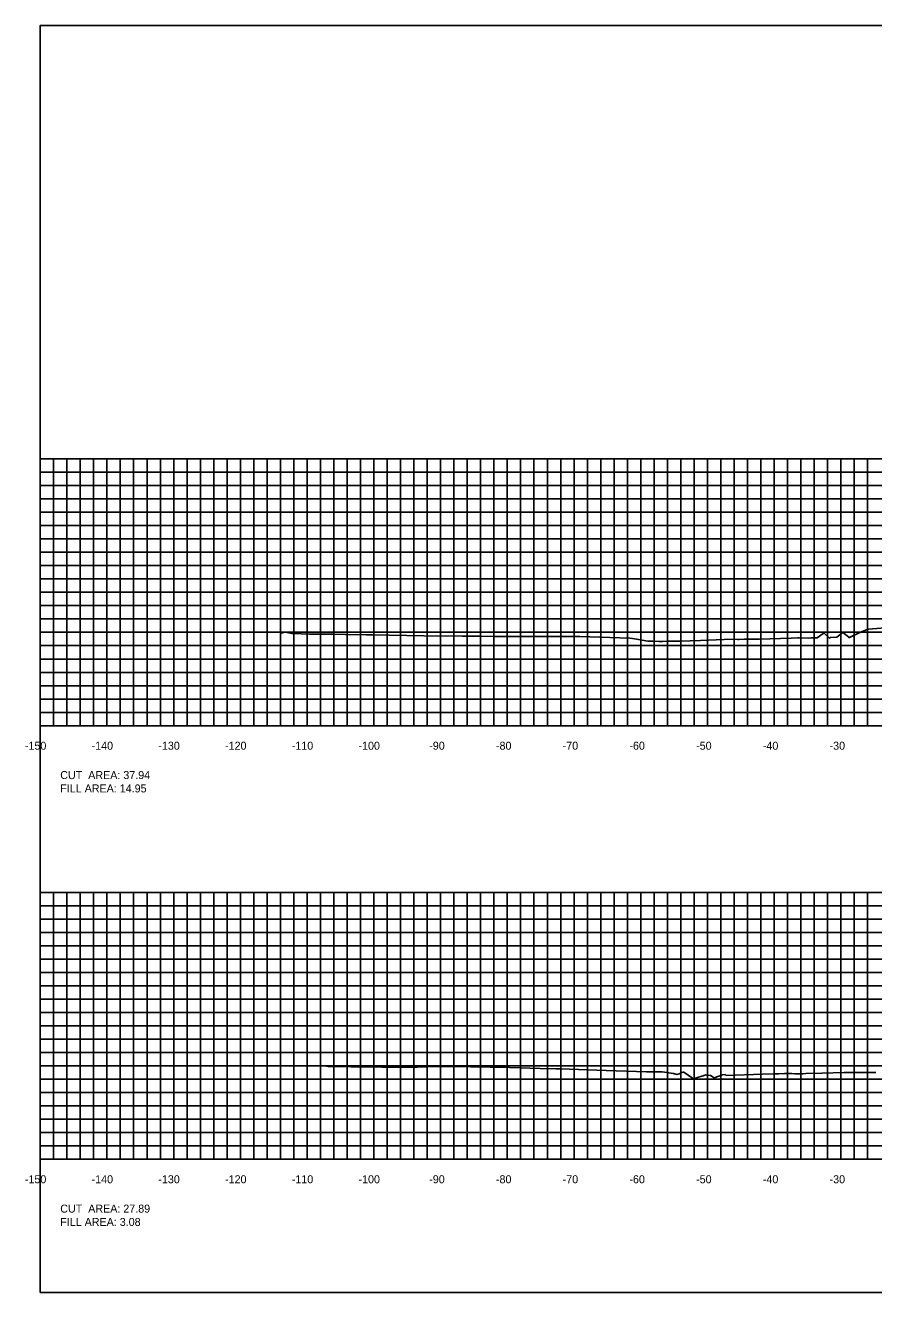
# Model space of a CAD drawing. Extents: x 1797652 to 1804159, y 242516 to 246906.
# Drawn here: x 1802492.3 to 1802619.4, y 242516 to 242706 of the extents above; entities that cross this region are included whole.
import ezdxf

# ---------------------------------------------------------------- set-up
doc = ezdxf.new("R2010")
doc.units = 0
for name, color, linetype in [('10', 7, 'Continuous'), ('60', 7, 'Continuous'), ('Level 62', 7, 'Continuous'), ('M-ROADS', 7, 'Continuous')]:
    doc.layers.add(name, color=color, linetype=linetype)

msp = doc.modelspace()

# ---------------------------------------------------------------- linework, layer by layer
msp.add_lwpolyline([(1802494.49, 242516), (1802794.49, 242516), (1802794.49, 242706), (1802494.49, 242706)], close=True)
at = {"layer": '60'}
for p, q in [((1802494.43, 242641), (1802494.49, 242641)), ((1802494.49, 242601), (1802494.49, 242641)), ((1802494.43, 242631), (1802494.49, 242631)), ((1802494.43, 242621), (1802494.49, 242621)), ((1802494.43, 242611), (1802494.49, 242611)), ((1802494.43, 242601), (1802494.49, 242601)), ((1802494.49, 242601), (1802794.49, 242601)), ((1802494.49, 242600.94), (1802494.49, 242601)), ((1802504.49, 242600.94), (1802504.49, 242601)), ((1802514.49, 242600.94), (1802514.49, 242601)), ((1802524.49, 242600.94), (1802524.49, 242601)), ((1802534.49, 242600.94), (1802534.49, 242601)), ((1802544.49, 242600.94), (1802544.49, 242601)), ((1802554.49, 242600.94), (1802554.49, 242601)), ((1802564.49, 242600.94), (1802564.49, 242601)), ((1802574.49, 242600.94), (1802574.49, 242601)), ((1802584.49, 242600.94), (1802584.49, 242601)), ((1802594.49, 242600.94), (1802594.49, 242601)), ((1802604.49, 242600.94), (1802604.49, 242601)), ((1802614.49, 242600.94), (1802614.49, 242601)), ((1802494.43, 242576), (1802494.49, 242576)), ((1802494.49, 242536), (1802494.49, 242576)), ((1802494.43, 242566), (1802494.49, 242566)), ((1802494.43, 242556), (1802494.49, 242556)), ((1802494.43, 242546), (1802494.49, 242546)), ((1802494.43, 242536), (1802494.49, 242536)), ((1802494.49, 242536), (1802794.49, 242536)), ((1802494.49, 242535.94), (1802494.49, 242536)), ((1802504.49, 242535.94), (1802504.49, 242536)), ((1802514.49, 242535.94), (1802514.49, 242536)), ((1802524.49, 242535.94), (1802524.49, 242536)), ((1802534.49, 242535.94), (1802534.49, 242536)), ((1802544.49, 242535.94), (1802544.49, 242536)), ((1802554.49, 242535.94), (1802554.49, 242536)), ((1802564.49, 242535.94), (1802564.49, 242536)), ((1802574.49, 242535.94), (1802574.49, 242536)), ((1802584.49, 242535.94), (1802584.49, 242536)), ((1802594.49, 242535.94), (1802594.49, 242536)), ((1802604.49, 242535.94), (1802604.49, 242536)), ((1802614.49, 242535.94), (1802614.49, 242536))]:
    msp.add_line(p, q, dxfattribs=at)
at = {"layer": 'Level 62'}
for p, q in [((1802494.49, 242641), (1802794.49, 242641)), ((1802494.49, 242601), (1802494.49, 242641)), ((1802496.49, 242601), (1802496.49, 242641)), ((1802498.49, 242601), (1802498.49, 242641)), ((1802500.49, 242601), (1802500.49, 242641)), ((1802502.49, 242601), (1802502.49, 242641)), ((1802504.49, 242601), (1802504.49, 242641)), ((1802506.49, 242601), (1802506.49, 242641)), ((1802508.49, 242601), (1802508.49, 242641)), ((1802510.49, 242601), (1802510.49, 242641)), ((1802512.49, 242601), (1802512.49, 242641)), ((1802514.49, 242601), (1802514.49, 242641)), ((1802516.49, 242601), (1802516.49, 242641)), ((1802518.49, 242601), (1802518.49, 242641)), ((1802520.49, 242601), (1802520.49, 242641)), ((1802522.49, 242601), (1802522.49, 242641)), ((1802524.49, 242601), (1802524.49, 242641)), ((1802526.49, 242601), (1802526.49, 242641)), ((1802528.49, 242601), (1802528.49, 242641)), ((1802530.49, 242601), (1802530.49, 242641)), ((1802532.49, 242601), (1802532.49, 242641)), ((1802534.49, 242601), (1802534.49, 242641)), ((1802536.49, 242601), (1802536.49, 242641)), ((1802538.49, 242601), (1802538.49, 242641)), ((1802540.49, 242601), (1802540.49, 242641)), ((1802542.49, 242601), (1802542.49, 242641)), ((1802544.49, 242601), (1802544.49, 242641)), ((1802546.49, 242601), (1802546.49, 242641)), ((1802548.49, 242601), (1802548.49, 242641)), ((1802550.49, 242601), (1802550.49, 242641)), ((1802552.49, 242601), (1802552.49, 242641)), ((1802554.49, 242601), (1802554.49, 242641)), ((1802556.49, 242601), (1802556.49, 242641)), ((1802558.49, 242601), (1802558.49, 242641)), ((1802560.49, 242601), (1802560.49, 242641)), ((1802562.49, 242601), (1802562.49, 242641)), ((1802564.49, 242601), (1802564.49, 242641)), ((1802566.49, 242601), (1802566.49, 242641)), ((1802568.49, 242601), (1802568.49, 242641)), ((1802570.49, 242601), (1802570.49, 242641)), ((1802572.49, 242601), (1802572.49, 242641)), ((1802574.49, 242601), (1802574.49, 242641)), ((1802576.49, 242601), (1802576.49, 242641)), ((1802578.49, 242601), (1802578.49, 242641)), ((1802580.49, 242601), (1802580.49, 242641)), ((1802582.49, 242601), (1802582.49, 242641)), ((1802584.49, 242601), (1802584.49, 242641)), ((1802586.49, 242601), (1802586.49, 242641)), ((1802588.49, 242601), (1802588.49, 242641)), ((1802590.49, 242601), (1802590.49, 242641)), ((1802592.49, 242601), (1802592.49, 242641)), ((1802594.49, 242601), (1802594.49, 242641)), ((1802596.49, 242601), (1802596.49, 242641)), ((1802598.49, 242601), (1802598.49, 242641)), ((1802600.49, 242601), (1802600.49, 242641)), ((1802602.49, 242601), (1802602.49, 242641)), ((1802604.49, 242601), (1802604.49, 242641)), ((1802606.49, 242601), (1802606.49, 242641)), ((1802608.49, 242601), (1802608.49, 242641)), ((1802610.49, 242601), (1802610.49, 242641)), ((1802612.49, 242601), (1802612.49, 242641)), ((1802614.49, 242601), (1802614.49, 242641)), ((1802616.49, 242601), (1802616.49, 242641)), ((1802618.49, 242601), (1802618.49, 242641)), ((1802494.49, 242639), (1802794.49, 242639)), ((1802494.49, 242637), (1802794.49, 242637)), ((1802494.49, 242635), (1802794.49, 242635)), ((1802494.49, 242633), (1802794.49, 242633)), ((1802494.49, 242631), (1802794.49, 242631)), ((1802494.49, 242629), (1802794.49, 242629)), ((1802494.49, 242627), (1802794.49, 242627)), ((1802494.49, 242625), (1802794.49, 242625)), ((1802494.49, 242623), (1802794.49, 242623)), ((1802494.49, 242621), (1802794.49, 242621)), ((1802494.49, 242619), (1802794.49, 242619)), ((1802494.49, 242617), (1802794.49, 242617)), ((1802494.49, 242615), (1802794.49, 242615)), ((1802494.49, 242613), (1802794.49, 242613)), ((1802494.49, 242611), (1802794.49, 242611)), ((1802494.49, 242609), (1802794.49, 242609)), ((1802494.49, 242607), (1802794.49, 242607)), ((1802494.49, 242605), (1802794.49, 242605)), ((1802494.49, 242603), (1802794.49, 242603)), ((1802494.49, 242601), (1802794.49, 242601)), ((1802494.49, 242576), (1802794.49, 242576)), ((1802494.49, 242536), (1802494.49, 242576)), ((1802496.49, 242536), (1802496.49, 242576)), ((1802498.49, 242536), (1802498.49, 242576)), ((1802500.49, 242536), (1802500.49, 242576)), ((1802502.49, 242536), (1802502.49, 242576)), ((1802504.49, 242536), (1802504.49, 242576)), ((1802506.49, 242536), (1802506.49, 242576)), ((1802508.49, 242536), (1802508.49, 242576)), ((1802510.49, 242536), (1802510.49, 242576)), ((1802512.49, 242536), (1802512.49, 242576)), ((1802514.49, 242536), (1802514.49, 242576)), ((1802516.49, 242536), (1802516.49, 242576)), ((1802518.49, 242536), (1802518.49, 242576)), ((1802520.49, 242536), (1802520.49, 242576)), ((1802522.49, 242536), (1802522.49, 242576)), ((1802524.49, 242536), (1802524.49, 242576)), ((1802526.49, 242536), (1802526.49, 242576)), ((1802528.49, 242536), (1802528.49, 242576)), ((1802530.49, 242536), (1802530.49, 242576)), ((1802532.49, 242536), (1802532.49, 242576)), ((1802534.49, 242536), (1802534.49, 242576)), ((1802536.49, 242536), (1802536.49, 242576)), ((1802538.49, 242536), (1802538.49, 242576)), ((1802540.49, 242536), (1802540.49, 242576)), ((1802542.49, 242536), (1802542.49, 242576)), ((1802544.49, 242536), (1802544.49, 242576)), ((1802546.49, 242536), (1802546.49, 242576)), ((1802548.49, 242536), (1802548.49, 242576)), ((1802550.49, 242536), (1802550.49, 242576)), ((1802552.49, 242536), (1802552.49, 242576)), ((1802554.49, 242536), (1802554.49, 242576)), ((1802556.49, 242536), (1802556.49, 242576)), ((1802558.49, 242536), (1802558.49, 242576)), ((1802560.49, 242536), (1802560.49, 242576)), ((1802562.49, 242536), (1802562.49, 242576)), ((1802564.49, 242536), (1802564.49, 242576)), ((1802566.49, 242536), (1802566.49, 242576)), ((1802568.49, 242536), (1802568.49, 242576)), ((1802570.49, 242536), (1802570.49, 242576)), ((1802572.49, 242536), (1802572.49, 242576)), ((1802574.49, 242536), (1802574.49, 242576)), ((1802576.49, 242536), (1802576.49, 242576)), ((1802578.49, 242536), (1802578.49, 242576)), ((1802580.49, 242536), (1802580.49, 242576)), ((1802582.49, 242536), (1802582.49, 242576)), ((1802584.49, 242536), (1802584.49, 242576)), ((1802586.49, 242536), (1802586.49, 242576)), ((1802588.49, 242536), (1802588.49, 242576)), ((1802590.49, 242536), (1802590.49, 242576)), ((1802592.49, 242536), (1802592.49, 242576)), ((1802594.49, 242536), (1802594.49, 242576)), ((1802596.49, 242536), (1802596.49, 242576)), ((1802598.49, 242536), (1802598.49, 242576)), ((1802600.49, 242536), (1802600.49, 242576)), ((1802602.49, 242536), (1802602.49, 242576)), ((1802604.49, 242536), (1802604.49, 242576)), ((1802606.49, 242536), (1802606.49, 242576)), ((1802608.49, 242536), (1802608.49, 242576)), ((1802610.49, 242536), (1802610.49, 242576)), ((1802612.49, 242536), (1802612.49, 242576)), ((1802614.49, 242536), (1802614.49, 242576)), ((1802616.49, 242536), (1802616.49, 242576)), ((1802618.49, 242536), (1802618.49, 242576)), ((1802494.49, 242574), (1802794.49, 242574)), ((1802494.49, 242572), (1802794.49, 242572)), ((1802494.49, 242570), (1802794.49, 242570)), ((1802494.49, 242568), (1802794.49, 242568)), ((1802494.49, 242566), (1802794.49, 242566)), ((1802494.49, 242564), (1802794.49, 242564)), ((1802494.49, 242562), (1802794.49, 242562)), ((1802494.49, 242560), (1802794.49, 242560)), ((1802494.49, 242558), (1802794.49, 242558)), ((1802494.49, 242556), (1802794.49, 242556)), ((1802494.49, 242554), (1802794.49, 242554)), ((1802494.49, 242552), (1802794.49, 242552)), ((1802494.49, 242550), (1802794.49, 242550)), ((1802494.49, 242548), (1802794.49, 242548)), ((1802494.49, 242546), (1802794.49, 242546)), ((1802494.49, 242544), (1802794.49, 242544)), ((1802494.49, 242542), (1802794.49, 242542)), ((1802494.49, 242540), (1802794.49, 242540)), ((1802494.49, 242538), (1802794.49, 242538)), ((1802494.49, 242536), (1802794.49, 242536))]:
    msp.add_line(p, q, dxfattribs=at)
at = {"layer": 'M-ROADS'}
for points in [[(1802530.58, 242614.89), (1802531.17, 242615.01), (1802532.24, 242614.8), (1802533.61, 242614.75), (1802534.86, 242614.74), (1802536.29, 242614.74), (1802537.79, 242614.72), (1802538.46, 242614.71), (1802540.22, 242614.66), (1802543.33, 242614.64), (1802544.3, 242614.64), (1802552, 242614.46), (1802557.77, 242614.42), (1802560.43, 242614.41), (1802562.54, 242614.38), (1802565.66, 242614.39), (1802565.87, 242614.39), (1802565.94, 242614.39), (1802574, 242614.39), (1802575.38, 242614.36), (1802582.84, 242614.11), (1802583.27, 242614.05), (1802584.14, 242613.9), (1802585.57, 242613.66), (1802586.28, 242613.65), (1802587.18, 242613.64), (1802587.75, 242613.64), (1802588.59, 242613.67), (1802588.68, 242613.67), (1802588.74, 242613.67), (1802589.05, 242613.67), (1802590.35, 242613.65), (1802593.44, 242613.78), (1802596.98, 242613.94), (1802597.5, 242613.95), (1802599.05, 242613.94), (1802599.11, 242613.94), (1802599.24, 242613.94), (1802600.01, 242613.96), (1802600.67, 242613.95), (1802601.36, 242613.95), (1802602.28, 242613.95), (1802607.02, 242614.12), (1802608.04, 242614.16), (1802608.23, 242614.16), (1802609.64, 242614.14), (1802610.02, 242614.15), (1802610.57, 242614.15), (1802610.94, 242614.15), (1802611.84, 242614.82), (1802611.97, 242614.88), (1802612.8, 242614.14), (1802612.93, 242614.2), (1802613.87, 242614.28), (1802614.78, 242614.99), (1802615.62, 242614.32), (1802615.67, 242614.24), (1802615.79, 242614.2), (1802617.4, 242615.02), (1802618.55, 242615.45), (1802621.76, 242615.71)], [(1802537.38, 242549.94), (1802537.46, 242549.96), (1802537.62, 242549.93), (1802538.62, 242549.89), (1802539.67, 242549.91), (1802541.09, 242549.88), (1802545.66, 242549.81), (1802546.4, 242549.81), (1802549.99, 242549.79), (1802550.65, 242549.8), (1802550.99, 242549.81), (1802553.78, 242549.9), (1802556.78, 242549.91), (1802559.03, 242549.88), (1802564.8, 242549.75), (1802569.43, 242549.59), (1802571.77, 242549.58), (1802572.42, 242549.58), (1802579.3, 242549.32), (1802585.34, 242549.11), (1802586.18, 242549.11), (1802587.08, 242549.1), (1802587.71, 242549.12), (1802589.39, 242548.85), (1802589.91, 242548.73), (1802590.23, 242548.81), (1802590.73, 242549.06), (1802590.81, 242549.03), (1802590.87, 242549.08), (1802590.88, 242549.1), (1802590.95, 242549.08), (1802592.25, 242548.15), (1802592.35, 242548.05), (1802593.65, 242548.44), (1802593.84, 242548.49), (1802594.21, 242548.67), (1802594.88, 242548.56), (1802594.94, 242548.55), (1802595.47, 242548.22), (1802596.76, 242548.66), (1802597.13, 242548.69), (1802597.28, 242548.57), (1802602.74, 242548.77), (1802604.43, 242548.82), (1802605.19, 242548.83), (1802606.04, 242548.84), (1802606.19, 242548.84), (1802606.41, 242548.84), (1802607.13, 242548.84), (1802607.6, 242548.83), (1802608.76, 242548.83), (1802609.21, 242548.84), (1802611.63, 242548.92), (1802614.97, 242549.02), (1802615.59, 242549.03), (1802616.57, 242549.02), (1802617.11, 242549.02), (1802617.94, 242549.01), (1802618.06, 242549.01), (1802618.14, 242549.01), (1802618.59, 242549.02), (1802619.74, 242549.03)]]:
    msp.add_lwpolyline(points, dxfattribs=at)

# ---------------------------------------------------------------- texts
at = {"layer": '10'}
for s, p in [('-150', (1802492.19, 242597.4)), ('-140', (1802502.19, 242597.4)), ('-130', (1802512.19, 242597.4)), ('-120', (1802522.19, 242597.4)), ('-110', (1802532.19, 242597.4)), ('-100', (1802542.19, 242597.4)), ('-90', (1802552.79, 242597.4)), ('-80', (1802562.79, 242597.4)), ('-70', (1802572.79, 242597.4)), ('-60', (1802582.79, 242597.4)), ('-50', (1802592.79, 242597.4)), ('-40', (1802602.79, 242597.4)), ('-30', (1802612.79, 242597.4)), ('CUT  AREA: 37.94', (1802497.49, 242593)), ('FILL AREA: 14.95', (1802497.49, 242591)), ('-150', (1802492.19, 242532.4)), ('-140', (1802502.19, 242532.4)), ('-130', (1802512.19, 242532.4)), ('-120', (1802522.19, 242532.4)), ('-110', (1802532.19, 242532.4)), ('-100', (1802542.19, 242532.4)), ('-90', (1802552.79, 242532.4)), ('-80', (1802562.79, 242532.4)), ('-70', (1802572.79, 242532.4)), ('-60', (1802582.79, 242532.4)), ('-50', (1802592.79, 242532.4)), ('-40', (1802602.79, 242532.4)), ('-30', (1802612.79, 242532.4)), ('CUT  AREA: 27.89', (1802497.49, 242528)), ('FILL AREA: 3.08', (1802497.49, 242526))]:
    msp.add_text(s, height=1.2, dxfattribs=at).set_placement(p)
at = {"layer": '60'}
for p in [(1802494.49, 242601), (1802494.49, 242536)]:
    msp.add_text('-', height=0.0001, dxfattribs=at).set_placement(p)

doc.saveas('drawing.dxf')
